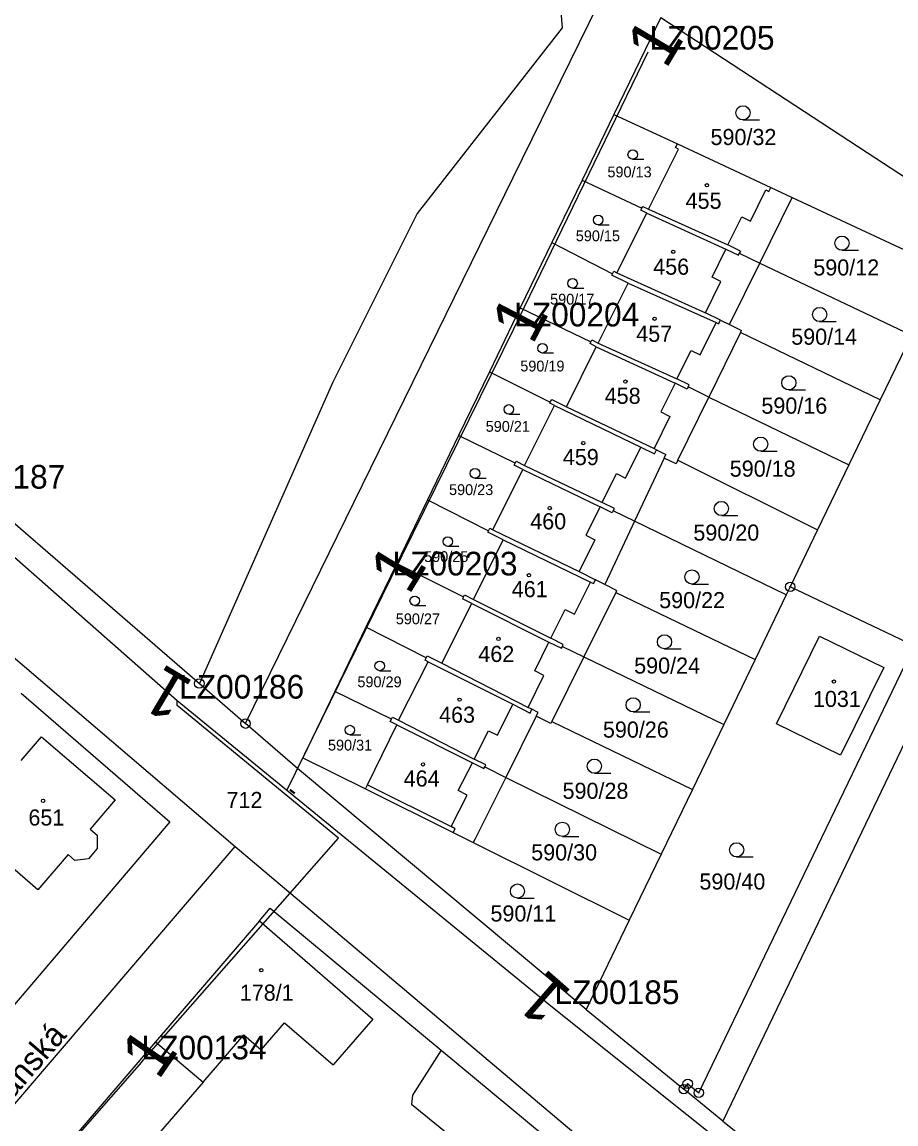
# Model space of a CAD drawing. Extents: x -738131 to -734179, y -1033447 to -1030078.
# Drawn here: x -735833.8 to -735741.5, y -1032462.8 to -1032346.5 of the extents above; entities that cross this region are included whole.
import ezdxf

# ---------------------------------------------------------------- set-up
doc = ezdxf.new("R2010")
doc.units = 0
for name, color, linetype in [('ftf_2010', 7, 'Continuous'), ('ftf_2210', 7, 'Continuous'), ('ftf_3010', 7, 'Continuous'), ('ftf_3010_ftf_3010_gtda_3015_gtda_3015_1', 7, 'Continuous'), ('ftf_nu', 7, 'Continuous'), ('Vrstva 1', 7, 'Continuous'), ('Vrstva 2', 7, 'Continuous'), ('Vrstva 3', 7, 'Continuous'), ('Vrstva 4', 7, 'Continuous'), ('Vrstva 5', 7, 'Continuous'), ('Vrstva 8', 7, 'Continuous')]:
    doc.layers.add(name, color=color, linetype=linetype)

msp = doc.modelspace()

# ---------------------------------------------------------------- linework, layer by layer
at = {"layer": 'ftf_2010'}
for points in [[(-735767.69, -1032349.68), (-735781.89, -1032378.92)], [(-735781.89, -1032378.92), (-735794.83, -1032405.22)], [(-735842.62, -1032395.9), (-735817.38, -1032418.12)], [(-735794.83, -1032405.22), (-735805.8, -1032427.57)], [(-735821.15, -1032456.3), (-735800.35, -1032432.64), (-735817.39, -1032418.65), (-735817.38, -1032418.12)], [(-735817.38, -1032418.12), (-735777.75, -1032450.49)], [(-735777.75, -1032450.49), (-735735.23, -1032484.5)], [(-735821.15, -1032456.3), (-735847.57, -1032486.43)]]:
    msp.add_lwpolyline(points, dxfattribs=at)
at = {"layer": 'Vrstva 1'}
for points in [[(-735926.61, -1032334.96), (-735811.27, -1032433.53)], [(-735777.54, -1032337.16), (-735776.74, -1032347.1)], [(-735781.92, -1032362.89), (-735772.9, -1032344.56)], [(-735766.33, -1032346.02), (-735771.27, -1032356.24)], [(-735766.33, -1032346.02), (-735743.64, -1032360.86)], [(-735776.74, -1032347.1), (-735792.03, -1032366.69)], [(-735888.01, -1032353.15), (-735815.04, -1032416.33)], [(-735771.27, -1032356.24), (-735774.64, -1032363.2)], [(-735771.27, -1032356.24), (-735764.57, -1032359.36)], [(-735764.77, -1032359.75), (-735764.57, -1032359.36)], [(-735764.57, -1032359.36), (-735754.71, -1032363.95)], [(-735767.62, -1032366.26), (-735764.45, -1032359.91)], [(-735764.45, -1032359.91), (-735764.77, -1032359.75)], [(-735743.64, -1032360.86), (-735733.92, -1032367.21)], [(-735810.16, -1032420.56), (-735781.92, -1032362.89)], [(-735774.64, -1032363.2), (-735777.83, -1032369.78)], [(-735774.64, -1032363.2), (-735768.34, -1032366.15)], [(-735754.71, -1032363.95), (-735752.45, -1032365.01)], [(-735755.89, -1032371.96), (-735752.45, -1032365.01)], [(-735752.45, -1032365.01), (-735736.45, -1032372.46)], [(-735768.44, -1032366.35), (-735768.34, -1032366.15)], [(-735767.82, -1032366.66), (-735768.44, -1032366.35)], [(-735768.34, -1032366.15), (-735768.24, -1032365.95)], [(-735768.24, -1032365.95), (-735767.62, -1032366.26)], [(-735792.03, -1032366.69), (-735800.94, -1032384.5)], [(-735770.96, -1032372.97), (-735767.82, -1032366.66)], [(-735767.82, -1032366.66), (-735759.45, -1032370.47)], [(-735777.83, -1032369.78), (-735781.16, -1032376.67)], [(-735777.83, -1032369.78), (-735771.42, -1032373.06)], [(-735759.45, -1032370.47), (-735758.14, -1032371.12)], [(-735758.14, -1032371.12), (-735758.04, -1032370.91)], [(-735758.04, -1032370.91), (-735755.89, -1032371.96)], [(-735759.09, -1032378.43), (-735755.89, -1032371.96)], [(-735755.89, -1032371.96), (-735739.86, -1032379.54)], [(-735771.5, -1032373.21), (-735771.42, -1032373.06)], [(-735769.78, -1032374.06), (-735771.5, -1032373.21)], [(-735771.42, -1032373.06), (-735771.3, -1032372.8)], [(-735771.3, -1032372.8), (-735770.96, -1032372.97)], [(-735772.93, -1032380.38), (-735769.78, -1032374.06)], [(-735769.78, -1032374.06), (-735760.5, -1032378.23)], [(-735781.16, -1032376.67), (-735784.42, -1032383.41)], [(-735781.16, -1032376.67), (-735773.7, -1032380.24)], [(-735760.23, -1032378.37), (-735760.03, -1032377.96)], [(-735760.03, -1032377.96), (-735759.09, -1032378.43)], [(-735718.91, -1032377.32), (-735749.73, -1032441.59)], [(-735760.5, -1032378.23), (-735760.23, -1032378.37)], [(-735759.09, -1032378.43), (-735757.81, -1032379.07)], [(-735757.91, -1032379.28), (-735757.81, -1032379.07)], [(-735773.8, -1032380.44), (-735773.7, -1032380.24)], [(-735773.7, -1032380.24), (-735773.6, -1032380.04)], [(-735773.6, -1032380.04), (-735772.93, -1032380.38)], [(-735757.91, -1032379.28), (-735761.26, -1032386.1)], [(-735743.16, -1032386.39), (-735757.91, -1032379.28)], [(-735739.86, -1032379.54), (-735743.16, -1032386.39)], [(-735776.29, -1032387.1), (-735773.14, -1032380.77)], [(-735773.14, -1032380.77), (-735773.8, -1032380.44)], [(-735773.14, -1032380.77), (-735764.82, -1032384.6)], [(-735784.42, -1032383.41), (-735787.68, -1032390.15)], [(-735784.42, -1032383.41), (-735777.99, -1032386.63)], [(-735800.94, -1032384.5), (-735815.04, -1032416.33)], [(-735763.54, -1032385.24), (-735764.82, -1032384.6)], [(-735764.52, -1032392.73), (-735761.26, -1032386.1)], [(-735763.43, -1032385.02), (-735763.54, -1032385.24)], [(-735761.26, -1032386.1), (-735763.43, -1032385.02)], [(-735761.26, -1032386.1), (-735746.47, -1032393.25)], [(-735780.71, -1032393.3), (-735777.56, -1032386.97)], [(-735778.04, -1032386.73), (-735777.99, -1032386.63)], [(-735777.56, -1032386.97), (-735778.04, -1032386.73)], [(-735777.99, -1032386.63), (-735777.84, -1032386.33)], [(-735777.84, -1032386.33), (-735776.29, -1032387.1)], [(-735777.56, -1032386.97), (-735768.43, -1032391.36)], [(-735743.16, -1032386.39), (-735746.47, -1032393.25)], [(-735787.68, -1032390.15), (-735790.96, -1032396.93)], [(-735781.71, -1032393.06), (-735787.68, -1032390.15)], [(-735768.43, -1032391.36), (-735766.98, -1032392.08)], [(-735766.98, -1032392.08), (-735766.77, -1032391.66)], [(-735766.77, -1032391.66), (-735765.79, -1032392.14)], [(-735781.81, -1032393.26), (-735781.71, -1032393.06)], [(-735781.71, -1032393.06), (-735781.61, -1032392.86)], [(-735781.61, -1032392.86), (-735780.71, -1032393.3)], [(-735765.98, -1032392.55), (-735769.11, -1032399.19)], [(-735765.98, -1032392.55), (-735765.79, -1032392.14)], [(-735764.72, -1032393.14), (-735765.98, -1032392.55)], [(-735764.52, -1032392.73), (-735764.72, -1032393.14)], [(-735764.52, -1032392.73), (-735749.78, -1032400.1)], [(-735784.07, -1032400.1), (-735780.89, -1032393.72)], [(-735780.89, -1032393.72), (-735781.81, -1032393.26)], [(-735780.89, -1032393.72), (-735772.74, -1032397.67)], [(-735746.47, -1032393.25), (-735749.78, -1032400.1)], [(-735790.96, -1032396.93), (-735794.2, -1032403.64)], [(-735790.96, -1032396.93), (-735784.52, -1032400.22)], [(-735771.45, -1032398.3), (-735772.74, -1032397.67)], [(-735771.34, -1032398.08), (-735771.45, -1032398.3)], [(-735769.11, -1032399.19), (-735771.34, -1032398.08)], [(-735784.52, -1032400.22), (-735784.38, -1032399.94)], [(-735784.38, -1032399.94), (-735784.07, -1032400.1)], [(-735769.11, -1032399.19), (-735772.25, -1032405.86)], [(-735753.08, -1032406.95), (-735769.11, -1032399.19)], [(-735749.78, -1032400.1), (-735752.67, -1032406.11)], [(-735786.1, -1032407.46), (-735782.97, -1032401.17)], [(-735784.59, -1032400.36), (-735784.52, -1032400.22)], [(-735782.97, -1032401.17), (-735784.59, -1032400.36)], [(-735782.97, -1032401.17), (-735773.75, -1032405.62)], [(-735794.2, -1032403.64), (-735797.46, -1032410.38)], [(-735794.2, -1032403.64), (-735787.15, -1032407.19)], [(-735773.75, -1032405.62), (-735773.44, -1032405.78)], [(-735773.44, -1032405.78), (-735773.23, -1032405.37)], [(-735772.25, -1032405.86), (-735773.23, -1032405.37)], [(-735770.99, -1032406.5), (-735772.25, -1032405.86)], [(-735787.15, -1032407.19), (-735787.05, -1032406.98)], [(-735787.05, -1032406.98), (-735786.1, -1032407.46)], [(-735771.09, -1032406.71), (-735774.46, -1032413.52)], [(-735770.99, -1032406.5), (-735771.09, -1032406.71)], [(-735771.09, -1032406.71), (-735756.38, -1032413.8)], [(-735753.08, -1032406.95), (-735756.38, -1032413.8)], [(-735752.67, -1032406.11), (-735753.08, -1032406.95)], [(-735739.59, -1032412.35), (-735752.67, -1032406.11)], [(-735789.44, -1032414.19), (-735786.29, -1032407.87)], [(-735787.15, -1032407.19), (-735787.25, -1032407.39)], [(-735786.29, -1032407.87), (-735787.25, -1032407.39)], [(-735786.29, -1032407.87), (-735778.14, -1032411.95)], [(-735797.46, -1032410.38), (-735800.75, -1032417.17)], [(-735791.08, -1032413.62), (-735797.46, -1032410.38)], [(-735754.11, -1032420.58), (-735749.59, -1032411.33)], [(-735749.59, -1032411.33), (-735742.78, -1032414.63)], [(-735778.14, -1032411.95), (-735776.82, -1032412.6)], [(-735776.82, -1032412.6), (-735776.72, -1032412.4)], [(-735776.72, -1032412.4), (-735774.46, -1032413.52)], [(-735762.32, -1032459.53), (-735739.59, -1032412.35)], [(-735794.01, -1032420.21), (-735790.87, -1032414.03)], [(-735791.2, -1032413.86), (-735791.08, -1032413.62)], [(-735790.87, -1032414.03), (-735791.2, -1032413.86)], [(-735791.08, -1032413.62), (-735790.98, -1032413.42)], [(-735790.98, -1032413.42), (-735789.44, -1032414.19)], [(-735790.87, -1032414.03), (-735781.93, -1032418.52)], [(-735774.46, -1032413.52), (-735777.83, -1032420.33)], [(-735774.46, -1032413.52), (-735759.68, -1032420.64)], [(-735756.38, -1032413.8), (-735759.68, -1032420.64)], [(-735742.78, -1032414.63), (-735747.35, -1032423.9)], [(-735815.04, -1032416.33), (-735810.16, -1032420.56)], [(-735833.85, -1032417.33), (-735818.17, -1032430.93)], [(-735800.75, -1032417.17), (-735804.13, -1032424.17)], [(-735794.77, -1032420.1), (-735800.75, -1032417.17)], [(-735781.93, -1032418.52), (-735780.13, -1032419.44)], [(-735794.77, -1032420.1), (-735794.66, -1032419.88)], [(-735794.66, -1032419.88), (-735794.01, -1032420.21)], [(-735779.47, -1032419.77), (-735782.7, -1032426.25)], [(-735780.13, -1032419.44), (-735779.93, -1032419.04)], [(-735779.28, -1032419.37), (-735779.93, -1032419.04)], [(-735779.47, -1032419.77), (-735779.28, -1032419.37)], [(-735777.93, -1032420.54), (-735779.47, -1032419.77)], [(-735804.68, -1032425.3), (-735810.16, -1032420.56)], [(-735797.29, -1032427.01), (-735794.18, -1032420.67)], [(-735794.88, -1032420.32), (-735794.77, -1032420.1)], [(-735794.18, -1032420.67), (-735794.88, -1032420.32)], [(-735794.18, -1032420.67), (-735786.21, -1032424.7)], [(-735777.83, -1032420.33), (-735777.93, -1032420.54)], [(-735777.83, -1032420.33), (-735762.99, -1032427.51)], [(-735759.68, -1032420.64), (-735762.99, -1032427.51)], [(-735747.35, -1032423.9), (-735754.11, -1032420.58)], [(-735833.86, -1032424.46), (-735831.69, -1032421.95)], [(-735831.69, -1032421.95), (-735823.92, -1032428.59)], [(-735804.13, -1032424.17), (-735804.68, -1032425.3)], [(-735804.13, -1032424.17), (-735797.51, -1032427.46)], [(-735774.19, -1032450.74), (-735804.68, -1032425.3)], [(-735786.21, -1032424.7), (-735785.01, -1032425.31)], [(-735785.01, -1032425.31), (-735784.91, -1032425.12)], [(-735784.91, -1032425.12), (-735782.7, -1032426.25)], [(-735782.7, -1032426.25), (-735785.91, -1032432.71)], [(-735782.7, -1032426.25), (-735766.28, -1032434.34)], [(-735797.51, -1032427.46), (-735797.29, -1032427.01)], [(-735797.51, -1032427.46), (-735788.25, -1032432.07)], [(-735762.99, -1032427.51), (-735766.28, -1032434.34)], [(-735823.92, -1032428.59), (-735826.56, -1032431.71)], [(-735832.1, -1032438.11), (-735839.86, -1032431.4)], [(-735818.17, -1032430.93), (-735837.79, -1032453.96)], [(-735826.56, -1032431.71), (-735825.83, -1032432.32)], [(-735825.83, -1032432.32), (-735825.82, -1032433.76)], [(-735788.25, -1032432.07), (-735786.12, -1032433.12)], [(-735883.82, -1032518.25), (-735811.27, -1032433.53)], [(-735825.82, -1032433.76), (-735826.74, -1032434.84)], [(-735811.27, -1032433.53), (-735736.15, -1032496.99)], [(-735785.91, -1032432.71), (-735786.12, -1032433.12)], [(-735786.12, -1032433.12), (-735769.65, -1032441.31)], [(-735828.89, -1032434.39), (-735832.1, -1032438.11)], [(-735828.17, -1032435), (-735828.89, -1032434.39)], [(-735826.74, -1032434.84), (-735828.17, -1032435)], [(-735766.28, -1032434.34), (-735769.65, -1032441.31)], [(-735808.69, -1032441.37), (-735807.55, -1032440.04)], [(-735807.55, -1032440.04), (-735789.52, -1032455.02)], [(-735808.69, -1032441.37), (-735819.66, -1032454.16)], [(-735769.65, -1032441.31), (-735774.19, -1032450.74)], [(-735749.73, -1032441.59), (-735759.77, -1032462.52)], [(-735774.19, -1032450.74), (-735763.9, -1032459.14)], [(-735819.66, -1032454.16), (-735833.05, -1032469.78)], [(-735789.52, -1032455.02), (-735792.54, -1032459.79)], [(-735789.52, -1032455.02), (-735769.63, -1032471.55)], [(-735763.9, -1032459.14), (-735763.49, -1032458.58)], [(-735759.77, -1032462.52), (-735763.9, -1032459.14)], [(-735763.49, -1032458.58), (-735762.32, -1032459.53)], [(-735792.54, -1032459.79), (-735792.66, -1032460.72)], [(-735792.66, -1032460.72), (-735783.75, -1032467.99)], [(-735759.77, -1032462.52), (-735717.94, -1032495.86)]]:
    msp.add_lwpolyline(points, dxfattribs=at)
at = {"layer": 'Vrstva 3'}
for p, q in [((-735757.66, -1032356.83), (-735755.91, -1032356.83)), ((-735769.3, -1032360.98), (-735768.12, -1032360.98)), ((-735772.95, -1032367.89), (-735771.77, -1032367.89)), ((-735747.21, -1032370.59), (-735745.46, -1032370.59)), ((-735775.65, -1032374.58), (-735774.47, -1032374.58)), ((-735749.56, -1032378.12), (-735747.81, -1032378.12)), ((-735778.83, -1032381.43), (-735777.65, -1032381.43)), ((-735752.81, -1032385.33), (-735751.06, -1032385.33)), ((-735782.38, -1032387.89), (-735781.2, -1032387.89)), ((-735755.78, -1032391.81), (-735754.03, -1032391.81)), ((-735785.95, -1032394.64), (-735784.77, -1032394.64)), ((-735759.93, -1032398.6), (-735758.18, -1032398.6)), ((-735788.82, -1032401.84), (-735787.64, -1032401.84)), ((-735763.04, -1032405.82), (-735761.29, -1032405.82)), ((-735792.31, -1032408.09), (-735791.13, -1032408.09)), ((-735765.94, -1032412.67), (-735764.19, -1032412.67)), ((-735796.01, -1032414.97), (-735794.83, -1032414.97)), ((-735769.25, -1032419.33), (-735767.5, -1032419.33)), ((-735799.16, -1032421.74), (-735797.98, -1032421.74)), ((-735773.34, -1032425.8), (-735771.59, -1032425.8)), ((-735776.72, -1032432.47), (-735774.97, -1032432.47)), ((-735758.33, -1032434.63), (-735756.58, -1032434.63)), ((-735781.46, -1032438.99), (-735779.71, -1032438.99))]:
    msp.add_line(p, q, dxfattribs=at)
for centre, radius in [((-735757.66, -1032356.08), 0.75), ((-735769.29, -1032360.48), 0.503), ((-735772.94, -1032367.39), 0.503), ((-735747.21, -1032369.84), 0.75), ((-735775.64, -1032374.08), 0.503), ((-735749.56, -1032377.37), 0.75), ((-735778.82, -1032380.93), 0.503), ((-735752.81, -1032384.58), 0.75), ((-735782.37, -1032387.39), 0.503), ((-735755.78, -1032391.06), 0.75), ((-735785.94, -1032394.14), 0.503), ((-735759.93, -1032397.85), 0.75), ((-735788.81, -1032401.34), 0.503), ((-735763.04, -1032405.07), 0.75), ((-735792.3, -1032407.59), 0.503), ((-735765.94, -1032411.92), 0.75), ((-735796, -1032414.47), 0.503), ((-735769.25, -1032418.58), 0.75), ((-735799.15, -1032421.24), 0.503), ((-735773.34, -1032425.05), 0.75), ((-735776.72, -1032431.72), 0.75), ((-735758.33, -1032433.88), 0.75), ((-735781.46, -1032438.24), 0.75)]:
    msp.add_circle(centre, radius, dxfattribs=at)
at = {"layer": 'Vrstva 4'}
for points in [[(-735754.92, -1032364.37), (-735754.71, -1032363.95)], [(-735756.86, -1032367.52), (-735755.23, -1032364.21)], [(-735755.23, -1032364.21), (-735754.92, -1032364.37)], [(-735767.62, -1032366.26), (-735759.26, -1032370.02)], [(-735759.26, -1032370.02), (-735757.79, -1032367.06)], [(-735757.79, -1032367.06), (-735756.86, -1032367.52)], [(-735760.91, -1032373.43), (-735759.45, -1032370.47)], [(-735757.93, -1032370.69), (-735759.26, -1032370.02)], [(-735757.93, -1032370.69), (-735758.04, -1032370.91)], [(-735770.96, -1032372.97), (-735761.61, -1032377.18)], [(-735761.61, -1032377.18), (-735759.98, -1032373.89)], [(-735759.98, -1032373.89), (-735760.91, -1032373.43)], [(-735760.03, -1032377.96), (-735761.61, -1032377.18)], [(-735762.19, -1032381.63), (-735760.5, -1032378.23)], [(-735772.93, -1032380.38), (-735764.62, -1032384.16)], [(-735764.62, -1032384.16), (-735763.13, -1032381.16)], [(-735763.13, -1032381.16), (-735762.19, -1032381.63)], [(-735764.82, -1032384.6), (-735766.34, -1032387.66)], [(-735763.32, -1032384.81), (-735764.62, -1032384.16)], [(-735763.43, -1032385.02), (-735763.32, -1032384.81)], [(-735776.29, -1032387.1), (-735767.04, -1032391.52)], [(-735765.36, -1032388.15), (-735767.04, -1032391.52)], [(-735766.34, -1032387.66), (-735765.36, -1032388.15)], [(-735770.06, -1032394.65), (-735768.43, -1032391.36)], [(-735767.04, -1032391.52), (-735766.77, -1032391.66)], [(-735780.71, -1032393.3), (-735772.53, -1032397.21)], [(-735772.53, -1032397.21), (-735771.02, -1032394.17)], [(-735771.02, -1032394.17), (-735770.06, -1032394.65)], [(-735772.74, -1032397.67), (-735774.23, -1032400.67)], [(-735771.23, -1032397.86), (-735772.53, -1032397.21)], [(-735771.34, -1032398.08), (-735771.23, -1032397.86)], [(-735784.07, -1032400.1), (-735774.96, -1032404.51)], [(-735773.29, -1032401.14), (-735774.96, -1032404.51)], [(-735774.23, -1032400.67), (-735773.29, -1032401.14)], [(-735774.96, -1032404.51), (-735773.23, -1032405.37)], [(-735775.45, -1032409.01), (-735773.75, -1032405.62)], [(-735786.1, -1032407.46), (-735777.93, -1032411.53)], [(-735777.93, -1032411.53), (-735776.41, -1032408.52)], [(-735776.41, -1032408.52), (-735775.45, -1032409.01)], [(-735776.62, -1032412.19), (-735777.93, -1032411.53)], [(-735779.64, -1032414.99), (-735778.14, -1032411.95)], [(-735776.72, -1032412.4), (-735776.62, -1032412.19)], [(-735789.44, -1032414.19), (-735780.33, -1032418.84)], [(-735778.66, -1032415.47), (-735779.64, -1032414.99)], [(-735780.33, -1032418.84), (-735778.66, -1032415.47)], [(-735783.58, -1032421.79), (-735781.93, -1032418.52)], [(-735779.93, -1032419.04), (-735780.33, -1032418.84)], [(-735794.01, -1032420.21), (-735786.02, -1032424.3)], [(-735786.02, -1032424.3), (-735784.51, -1032421.32)], [(-735784.51, -1032421.32), (-735783.58, -1032421.79)], [(-735784.81, -1032424.92), (-735786.02, -1032424.3)], [(-735787.71, -1032427.62), (-735786.21, -1032424.7)], [(-735784.91, -1032425.12), (-735784.81, -1032424.92)], [(-735797.29, -1032427.01), (-735788.47, -1032431.43)], [(-735786.76, -1032428.1), (-735787.71, -1032427.62)], [(-735788.47, -1032431.43), (-735786.76, -1032428.1)], [(-735788.04, -1032431.65), (-735788.47, -1032431.43)], [(-735788.25, -1032432.07), (-735788.04, -1032431.65)], [(-735808.69, -1032441.37), (-735796.73, -1032451.75)], [(-735808.53, -1032455.01), (-735806.05, -1032452.14)], [(-735806.05, -1032452.14), (-735800.9, -1032456.58)], [(-735796.73, -1032451.75), (-735800.9, -1032456.58)], [(-735814.65, -1032458.41), (-735810.36, -1032453.43)], [(-735810.36, -1032453.43), (-735808.53, -1032455.01)], [(-735819.66, -1032454.16), (-735814.65, -1032458.41)], [(-735814.65, -1032458.41), (-735824.28, -1032469.56)]]:
    msp.add_lwpolyline(points, dxfattribs=at)
at = {"layer": 'Vrstva 5'}
for centre in [(-735761.46, -1032363.73), (-735765.02, -1032370.75), (-735766.99, -1032377.82), (-735770.06, -1032384.45), (-735774.51, -1032390.94), (-735778.05, -1032397.81), (-735780.25, -1032404.89), (-735783.46, -1032411.61), (-735748.06, -1032416.12), (-735787.57, -1032418.03), (-735791.43, -1032424.87), (-735831.53, -1032428.71), (-735808.51, -1032446.59)]:
    msp.add_circle(centre, 0.175, dxfattribs=at)
at = {"layer": 'Vrstva 8'}
for centre, radius in [((-735752.67, -1032406.11), 0.5), ((-735752.67, -1032406.11), 0.0303), ((-735815.04, -1032416.33), 0.5), ((-735815.04, -1032416.33), 0.5), ((-735815.04, -1032416.33), 0.0303), ((-735815.04, -1032416.33), 0.0303), ((-735810.16, -1032420.56), 0.5), ((-735810.16, -1032420.56), 0.5), ((-735810.16, -1032420.56), 0.0303), ((-735810.16, -1032420.56), 0.0303), ((-735763.49, -1032458.58), 0.5), ((-735763.9, -1032459.14), 0.5), ((-735763.9, -1032459.14), 0.0303), ((-735763.49, -1032458.58), 0.0303), ((-735762.32, -1032459.53), 0.5), ((-735762.32, -1032459.53), 0.0303)]:
    msp.add_circle(centre, radius, dxfattribs=at)

# ---------------------------------------------------------------- texts
at = {"layer": 'ftf_2210'}
msp.add_text('-', height=2, rotation=142.5741, dxfattribs=at).set_placement((-735804.4, -1032427.39))
at = {"layer": 'ftf_3010'}
for rotation, p in [(59.232, (-735765.79, -1032351.57)), (62.5434, (-735779.88, -1032380.69)), (58.6956, (-735792.94, -1032407.12)), (149.2459, (-735815.49, -1032416.21)), (138.8674, (-735775.55, -1032448.96)), (55.4482, (-735819.38, -1032458.31))]:
    msp.add_text('1', height=5.2, rotation=rotation, dxfattribs=at).set_placement(p)
at = {"layer": 'ftf_3010_ftf_3010_gtda_3015_gtda_3015_1'}
for s, p in [('LZ00205', (-735767.52, -1032349.4)), ('LZ00204', (-735781.8, -1032378.63)), ('LZ00187', (-735842.39, -1032395.75)), ('LZ00203', (-735794.65, -1032404.92)), ('LZ00186', (-735817.17, -1032417.92)), ('LZ00185', (-735777.55, -1032450.17)), ('LZ00134', (-735821.14, -1032456.01))]:
    msp.add_text(s, height=2.5, dxfattribs=at).set_placement(p)
at = {"layer": 'ftf_nu'}
msp.add_text('Lánská', height=2.5, rotation=49.0615, dxfattribs=at).set_placement((-735836.01, -1032461.67))
at = {"layer": 'Vrstva 2'}
for s, height, p in [('590/32', 1.7, (-735761.08, -1032359.48)), ('590/13', 1.14, (-735771.96, -1032362.89)), ('455', 1.7, (-735763.71, -1032366.21)), ('590/15', 1.14, (-735775.3, -1032369.63)), ('456', 1.7, (-735767.13, -1032373.17)), ('590/12', 1.7, (-735750.23, -1032373.25)), ('590/17', 1.14, (-735778.01, -1032376.32)), ('457', 1.7, (-735768.92, -1032380.25)), ('590/14', 1.7, (-735752.56, -1032380.56)), ('590/19', 1.14, (-735781.16, -1032383.38)), ('458', 1.7, (-735772.25, -1032386.8)), ('590/16', 1.7, (-735755.71, -1032387.84)), ('590/21', 1.14, (-735784.81, -1032389.75)), ('459', 1.7, (-735776.67, -1032393.27)), ('590/18', 1.7, (-735759.05, -1032394.49)), ('590/23', 1.14, (-735788.68, -1032396.43)), ('460', 1.7, (-735780.11, -1032400.05)), ('590/20', 1.7, (-735762.89, -1032401.24)), ('590/25', 1.14, (-735791.31, -1032403.5)), ('461', 1.7, (-735782.06, -1032407.21)), ('590/22', 1.7, (-735766.5, -1032408.37)), ('590/27', 1.14, (-735794.3, -1032410.07)), ('462', 1.7, (-735785.59, -1032414.05)), ('590/24', 1.7, (-735769.14, -1032415.28)), ('590/29', 1.14, (-735798.35, -1032416.72)), ('1031', 1.7, (-735750.27, -1032418.8)), ('463', 1.7, (-735789.73, -1032420.47)), ('590/26', 1.7, (-735772.44, -1032422.04)), ('590/31', 1.14, (-735801.46, -1032423.4)), ('464', 1.7, (-735793.47, -1032427.2)), ('590/28', 1.7, (-735776.7, -1032428.5)), ('712', 1.7, (-735812.17, -1032429.47)), ('651', 1.7, (-735833.08, -1032431.32)), ('590/30', 1.7, (-735780.01, -1032435)), ('590/40', 1.7, (-735762.25, -1032438.08)), ('590/11', 1.7, (-735784.31, -1032441.45)), ('178/1', 1.7, (-735810.77, -1032449.81))]:
    msp.add_text(s, height=height, dxfattribs=at).set_placement(p)

doc.saveas('drawing.dxf')
